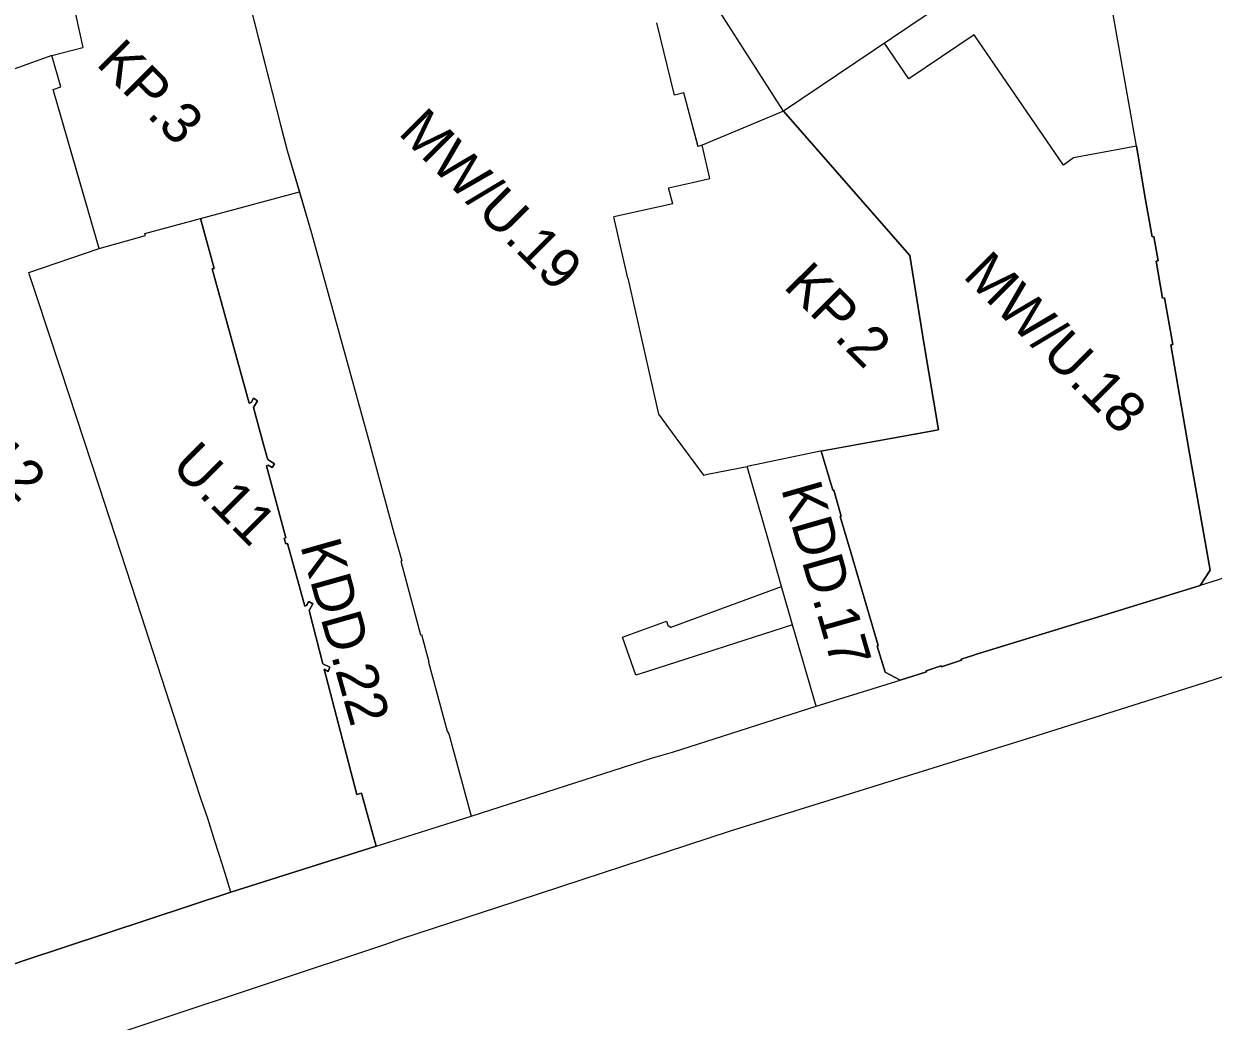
# Model space of a CAD drawing. Extents: x 7423835 to 7425280, y 5546086 to 5547600.
# Drawn here: x 7424593.5 to 7424769.7, y 5546498.6 to 5546646.4 of the extents above; entities that cross this region are included whole.
import ezdxf

# ---------------------------------------------------------------- set-up
doc = ezdxf.new("R2010")
doc.units = 0
for name, color, linetype in [('linie rozgraniczające', 7, 'Continuous'), ('nieprzekraczalne linie zabudowy', 7, 'Continuous'), ('obowiazujace linie zabudowy', 7, 'Continuous'), ('przeznaczenia terenów', 7, 'Continuous')]:
    doc.layers.add(name, color=color, linetype=linetype)

msp = doc.modelspace()

# ---------------------------------------------------------------- linework, layer by layer
at = {"layer": 'linie rozgraniczające'}
for p, q in [((7424600.28, 5546651.91), (7424602.25, 5546642.86)), ((7424758.3, 5546628.25), (7424754.02, 5546652.48)), ((7424706.02, 5546633.43), (7424696.68, 5546648.02)), ((7424597.65, 5546641.67), (7424602.25, 5546642.86)), ((7424706.02, 5546633.43), (7424693.96, 5546628.39)), ((7424724.74, 5546612.07), (7424706.02, 5546633.43)), ((7424619.66, 5546617.54), (7424634.32, 5546621.51)), ((7424689.64, 5546619.71), (7424680.92, 5546617.78)), ((7424711.75, 5546583.11), (7424700.63, 5546580.83)), ((7424710.85, 5546545.31), (7424723.33, 5546549.17)), ((7424645.69, 5546524.58), (7424659.78, 5546529.02))]:
    msp.add_line(p, q, dxfattribs=at)
for points in [[(7424754.02, 5546652.48), (7424727.46, 5546647.88), (7424706.02, 5546633.43)], [(7424626.99, 5546649.25), (7424631.53, 5546631.4), (7424632.5, 5546627.64), (7424636.13, 5546615.39), (7424644.82, 5546583.94), (7424648.31, 5546570.99), (7424649.49, 5546566.84), (7424649.34, 5546566.8), (7424652.28, 5546555.88), (7424652.43, 5546555.92), (7424653.51, 5546551.87), (7424653.43, 5546551.83), (7424656.2, 5546541.62), (7424656.47, 5546541.19), (7424659.78, 5546529.02), (7424686.48, 5546537.59), (7424689.61, 5546538.49), (7424710.85, 5546545.31), (7424707.38, 5546557.35), (7424705.75, 5546563.03), (7424703.88, 5546569.52), (7424702.02, 5546576.01), (7424700.63, 5546580.83)], [(7424689.64, 5546619.71), (7424688.98, 5546622.1), (7424692.55, 5546622.89), (7424695.12, 5546623.46), (7424693.96, 5546628.39), (7424693.39, 5546628.23), (7424692.31, 5546632.28), (7424691.27, 5546636.17), (7424689.87, 5546635.82), (7424687.29, 5546646.51)], [(7424604.68, 5546613.08), (7424597.85, 5546636.65), (7424599.01, 5546637.03), (7424597.65, 5546641.67), (7424579.79, 5546635.27), (7424557.12, 5546627.37)], [(7424758.3, 5546628.25), (7424759.66, 5546620.32), (7424760.62, 5546614.84), (7424760.88, 5546614.87), (7424761.51, 5546611.3), (7424761.21, 5546611.24), (7424762.18, 5546605.77), (7424762.48, 5546605.79), (7424763.71, 5546598.86), (7424763.4, 5546598.83), (7424766.05, 5546583.35), (7424769.21, 5546565.45), (7424767.74, 5546563.16)], [(7424604.68, 5546613.08), (7424611.52, 5546615.02), (7424611.44, 5546615.31), (7424619.66, 5546617.54), (7424621.71, 5546610.16), (7424621.42, 5546610.08), (7424626.87, 5546590.18), (7424627.16, 5546590.27), (7424627.54, 5546590.92), (7424628.1, 5546590.55), (7424627.53, 5546589.53), (7424629.03, 5546584.09), (7424629.56, 5546582.13), (7424629.64, 5546581.83), (7424630.08, 5546581.56), (7424630.65, 5546581.22), (7424630.29, 5546580.66), (7424629.68, 5546580.99), (7424629.44, 5546580.91), (7424632.34, 5546570.23), (7424632.08, 5546570.16), (7424632.3, 5546569.36), (7424632.55, 5546569.43), (7424635.11, 5546560.14), (7424635.36, 5546560.2), (7424635.73, 5546560.8), (7424636.31, 5546560.47), (7424635.75, 5546559.46), (7424637.79, 5546551.57), (7424638.82, 5546551.08), (7424638.58, 5546550.43), (7424637.97, 5546550.77), (7424642.81, 5546532.21), (7424643.53, 5546532.41), (7424645.69, 5546524.58), (7424624.19, 5546517.76)], [(7424682.96, 5546608.7), (7424681.5, 5546615.19), (7424680.92, 5546617.78)], [(7424624.19, 5546517.76), (7424624.19, 5546517.76), (7424623.53, 5546519.86), (7424622.87, 5546521.96), (7424621.82, 5546525.3), (7424620.76, 5546528.65), (7424619.8, 5546531.51), (7424618.84, 5546534.37), (7424614.55, 5546547.58), (7424610.26, 5546560.8), (7424604.65, 5546577.91), (7424599.03, 5546595.01), (7424596.97, 5546601.32), (7424595.64, 5546605.33), (7424594.31, 5546609.35), (7424594.24, 5546609.55), (7424604.68, 5546613.08)], [(7424767.74, 5546563.16), (7424751.23, 5546558.11), (7424751.05, 5546558.06), (7424734.45, 5546552.94), (7424734.21, 5546552.88), (7424732.36, 5546552.26), (7424732.41, 5546552.12), (7424729.43, 5546551.13), (7424729.38, 5546551.29), (7424727.15, 5546550.56), (7424727.19, 5546550.41), (7424723.33, 5546549.17), (7424721.09, 5546550.35), (7424719.9, 5546554.22), (7424720.07, 5546554.28), (7424716.03, 5546567.91), (7424714.44, 5546573.41), (7424714.58, 5546573.44), (7424713.47, 5546577.32), (7424713.35, 5546577.3), (7424711.67, 5546582.91), (7424711.75, 5546583.11), (7424728.99, 5546586.25), (7424726.82, 5546599.11), (7424724.74, 5546612.07)], [(7424682.96, 5546608.7), (7424687.49, 5546588.55), (7424687.49, 5546588.55), (7424690.1, 5546585.04), (7424694.18, 5546579.55)], [(7424918.4, 5546599.75), (7424918.38, 5546599.75), (7424900.98, 5546591.12), (7424878.58, 5546584.06), (7424866.75, 5546580.41), (7424855.79, 5546576.7), (7424832.92, 5546569.44), (7424821.32, 5546565.8), (7424799.61, 5546558.88), (7424787.74, 5546555.12), (7424771.89, 5546549.92), (7424768.38, 5546548.76), (7424743.55, 5546540.92), (7424698.14, 5546526.8), (7424663.53, 5546515.44), (7424659.14, 5546514), (7424649.3, 5546510.78), (7424646.94, 5546509.94), (7424595.52, 5546492.88), (7424562.11, 5546482.06)], [(7424694.18, 5546579.55), (7424694.75, 5546579.67), (7424700.63, 5546580.83)], [(7424786.43, 5546569.18), (7424783.77, 5546568.34), (7424769.33, 5546563.69), (7424767.74, 5546563.16)], [(7424624.19, 5546517.76), (7424593.56, 5546507.65), (7424588.76, 5546506.02), (7424587.64, 5546508.75)]]:
    msp.add_lwpolyline(points, dxfattribs=at)
at = {"layer": 'nieprzekraczalne linie zabudowy'}
for points in [[(7424734.29, 5546644.76), (7424724.58, 5546638.21), (7424721, 5546643.53)], [(7424747.48, 5546625.44), (7424734.29, 5546644.76)]]:
    msp.add_lwpolyline(points, dxfattribs=at)
at = {"layer": 'obowiazujace linie zabudowy'}
msp.add_line((7424706.02, 5546633.43), (7424724.74, 5546612.07), dxfattribs=at)
for points in [[(7424626.99, 5546649.25), (7424629.26, 5546640.33), (7424631.53, 5546631.4), (7424632.02, 5546629.52), (7424632.5, 5546627.64), (7424634.32, 5546621.51)], [(7424693.41, 5546628.16), (7424692.31, 5546632.28), (7424691.27, 5546636.17), (7424689.87, 5546635.82), (7424687.29, 5546646.51)], [(7424597.65, 5546641.67), (7424579.79, 5546635.27), (7424557.12, 5546627.37)], [(7424604.68, 5546613.08), (7424601.27, 5546624.87), (7424597.85, 5546636.65), (7424599.01, 5546637.03), (7424597.65, 5546641.67)], [(7424758.3, 5546628.25), (7424748.99, 5546626.53), (7424747.48, 5546625.44)], [(7424767.74, 5546563.16), (7424769.21, 5546565.45), (7424766.05, 5546583.35), (7424763.4, 5546598.83), (7424763.71, 5546598.86), (7424762.48, 5546605.79), (7424762.18, 5546605.77), (7424761.21, 5546611.24), (7424761.51, 5546611.3), (7424760.88, 5546614.87), (7424760.62, 5546614.84), (7424759.66, 5546620.32), (7424758.3, 5546628.25)], [(7424634.32, 5546621.51), (7424636.13, 5546615.39), (7424644.82, 5546583.94), (7424648.31, 5546570.99), (7424649.49, 5546566.84), (7424649.34, 5546566.8), (7424652.28, 5546555.88), (7424652.43, 5546555.92), (7424653.51, 5546551.87), (7424653.43, 5546551.83), (7424656.2, 5546541.62), (7424656.47, 5546541.19), (7424659.78, 5546529.02), (7424686.48, 5546537.59), (7424689.61, 5546538.49), (7424710.85, 5546545.31), (7424707.38, 5546557.35)], [(7424624.19, 5546517.76), (7424645.69, 5546524.58), (7424643.53, 5546532.41), (7424642.81, 5546532.21), (7424637.97, 5546550.77), (7424638.58, 5546550.43), (7424638.82, 5546551.08), (7424637.79, 5546551.57), (7424635.75, 5546559.46), (7424636.31, 5546560.47), (7424635.73, 5546560.8), (7424635.36, 5546560.2), (7424635.11, 5546560.14), (7424632.55, 5546569.43), (7424632.3, 5546569.36), (7424632.08, 5546570.16), (7424632.34, 5546570.23), (7424629.44, 5546580.91), (7424629.68, 5546580.99), (7424630.29, 5546580.66), (7424630.65, 5546581.22), (7424630.08, 5546581.56), (7424629.64, 5546581.83), (7424629.56, 5546582.13), (7424629.03, 5546584.09), (7424627.53, 5546589.53), (7424628.1, 5546590.55), (7424627.54, 5546590.92), (7424627.16, 5546590.27), (7424626.87, 5546590.18), (7424621.42, 5546610.08), (7424621.71, 5546610.16), (7424619.66, 5546617.54)], [(7424724.74, 5546612.07), (7424726.82, 5546599.11), (7424728.99, 5546586.25), (7424711.62, 5546583.09)], [(7424711.62, 5546583.09), (7424713.35, 5546577.3), (7424713.47, 5546577.32), (7424714.58, 5546573.44), (7424714.44, 5546573.41), (7424716.03, 5546567.91), (7424720.07, 5546554.28), (7424719.9, 5546554.22), (7424721.09, 5546550.35), (7424723.33, 5546549.17), (7424727.19, 5546550.41), (7424727.15, 5546550.56), (7424729.38, 5546551.29), (7424729.43, 5546551.13), (7424732.41, 5546552.12), (7424732.36, 5546552.26), (7424734.21, 5546552.88), (7424734.45, 5546552.94), (7424751.05, 5546558.06), (7424751.23, 5546558.11), (7424767.74, 5546563.16)], [(7424705.75, 5546563.03), (7424703.88, 5546569.52), (7424702.02, 5546576.01), (7424700.63, 5546580.83)], [(7424707.38, 5546557.35), (7424685.87, 5546550.43), (7424684.16, 5546549.88), (7424682.19, 5546555.55), (7424688.7, 5546557.91), (7424688.96, 5546557.15), (7424689.15, 5546557.22), (7424689.24, 5546556.95), (7424705.75, 5546563.03)], [(7424587.64, 5546508.75), (7424588.76, 5546506.02), (7424593.56, 5546507.65), (7424624.19, 5546517.76)]]:
    msp.add_lwpolyline(points, dxfattribs=at)

# ---------------------------------------------------------------- texts
at = {"layer": 'przeznaczenia terenów'}
for s, rotation, p in [('KP.3', 314.9764, (7424604.04, 5546640.35)), ('MW/U.19', 314.9764, (7424648.81, 5546630.11)), ('MW/U.18', 314.9764, (7424732.43, 5546608.92)), ('KP.2', 314.9764, (7424705.86, 5546607.35)), ('U.12', 314.9764, (7424581.01, 5546587.26)), ('U.11', 314.9764, (7424615.17, 5546580.69)), ('KDD.17', 285.9844, (7424705.64, 5546577.54)), ('KDD.22', 285.7133, (7424634.42, 5546569.11))]:
    msp.add_text(s, height=6, rotation=rotation, dxfattribs=at).set_placement(p)

doc.saveas('drawing.dxf')
